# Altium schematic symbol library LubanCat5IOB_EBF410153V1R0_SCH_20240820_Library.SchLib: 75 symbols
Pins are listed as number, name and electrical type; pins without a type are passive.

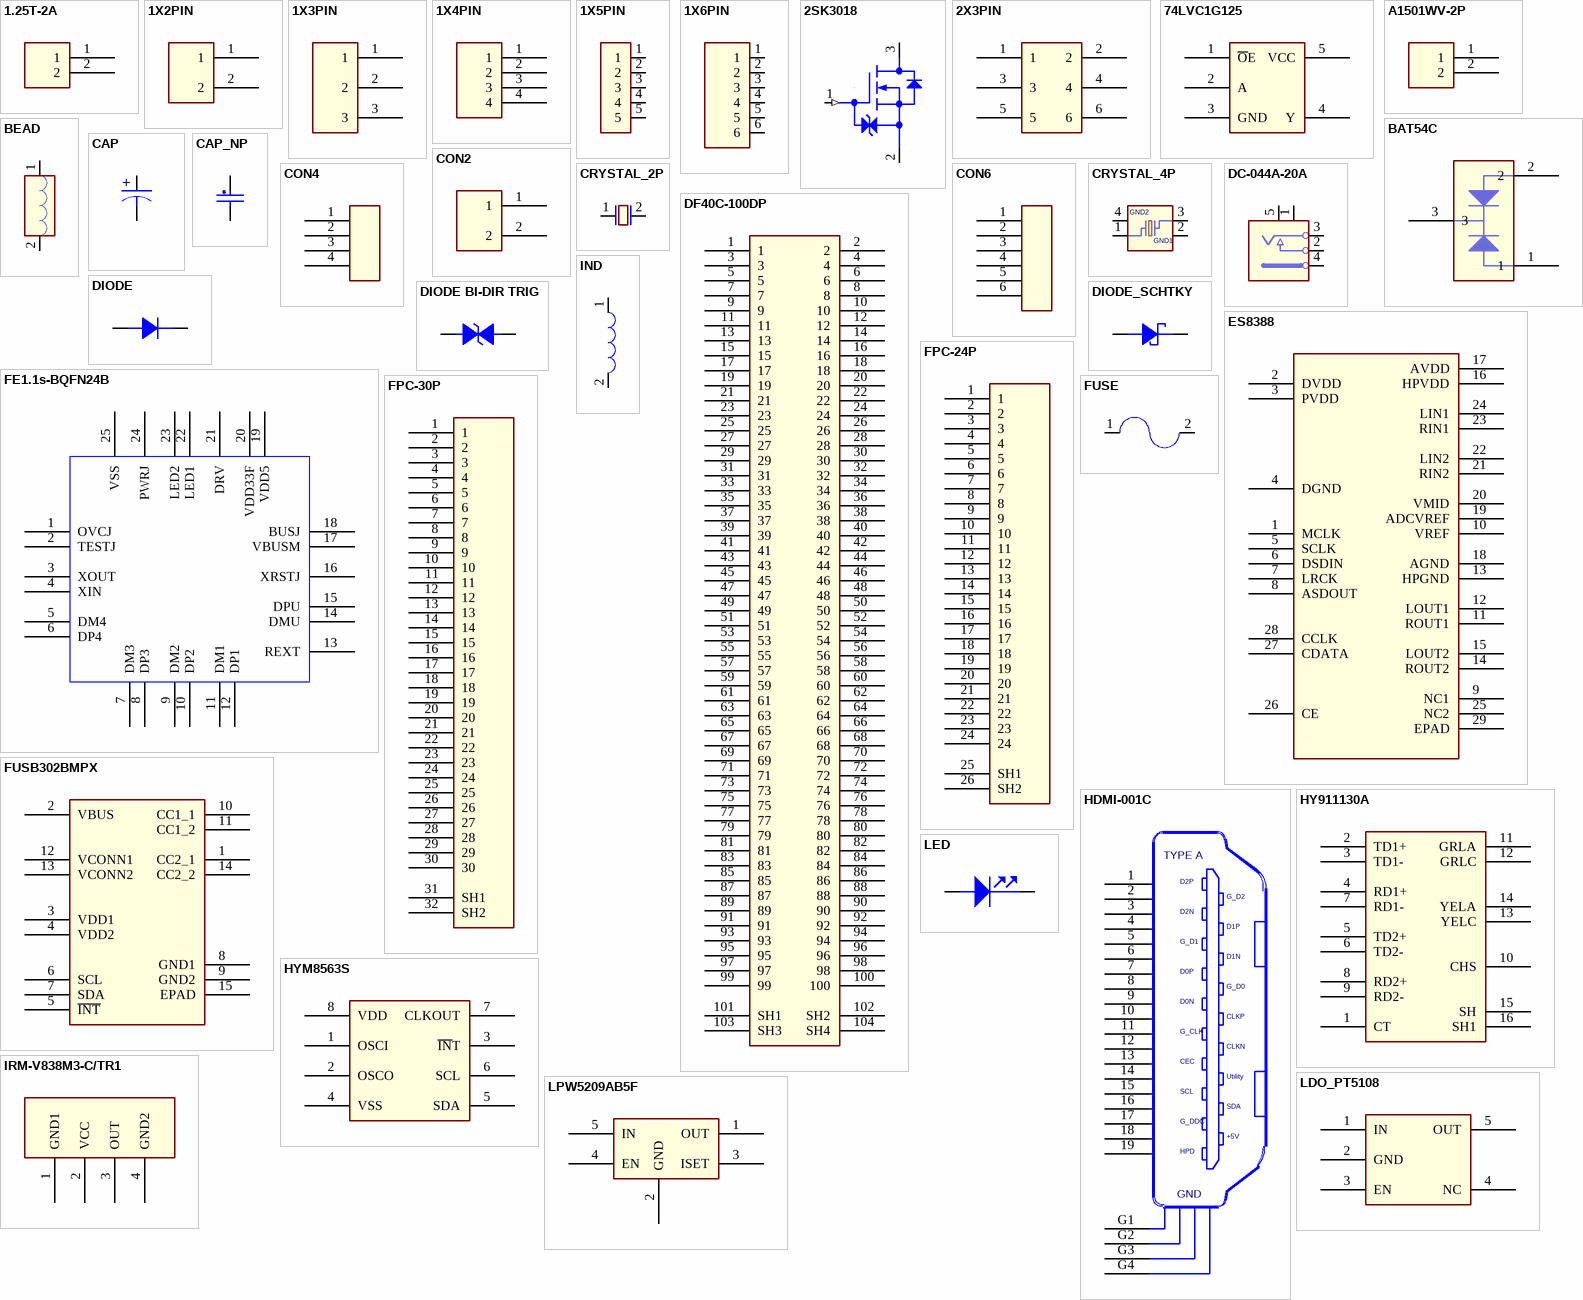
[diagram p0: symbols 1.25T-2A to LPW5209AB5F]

## 1.25T-2A
designator J?
footprint gh1p25_th_2p
pins: 1, 2

## 1X2PIN
designator J?
pins: 1, 2

## 1X3PIN
designator J?
pins: 1, 2, 3

## 1X4PIN
designator J?
pins: 1, 2, 3, 4

## 1X5PIN
designator J?
pins: 1, 2, 3, 4, 5

## 1X6PIN
designator J?
pins: 1, 2, 3, 4, 5, 6

## 2SK3018
designator Q?
CLASS: IC
pins: 1 GATE (in), 2 SOURCE, 3 DRAIN

## 2X3PIN
designator J?
pins: 1, 2, 3, 4, 5, 6

## 74LVC1G125
designator U?
footprint SOT-353
pins: 1 ~{O}E, 2 A, 3 GND, 4 Y, 5 VCC

## A1501WV-2P
designator J?
pins: 1, 2

## BAT54C
designator D?
footprint SOT23
pins: 1, 2, 3

## BEAD
designator L?
CLASS: DISCRETE
pins: 1, 2

## CAP
designator C?
footprint T2012
pins: 1, 2

## CAP_NP
designator C?
CLASS: DISCRETE
pins: 1, 2

## CON2
designator J?
pins: 1, 2

## CON4
designator J?
pins: 1, 2, 3, 4

## CON6
designator J?
pins: 1, 2, 3, 4, 5, 6

## CRYSTAL_2P
designator Y?
footprint 3215
pins: 1, 2

## CRYSTAL_4P
designator Y?
CLASS: IC
pins: 1, 2 GND1 (power), 3, 4 GND2 (power)

## DC-044A-20A
designator J?
footprint dc_in_th_3p_10r1x11r6
pins: 1, 2, 3, 4, 5

## DF40C-100DP
designator J?
pins: 1, 2, 3, 4, 5, 6, 7, 8, 9, 10, 11, 12, 13, 14, 15, 16, 17, 18, 19, 20, 21, 22, 23, 24, 25, 26, 27, 28, 29, 30, 31, 32, 33, 34, 35, 36, 37, 38, 39, 40, 41, 42, 43, 44, 45, 46, 47, 48, 49, 50, 51, 52, 53, 54, 55, 56, 57, 58, 59, 60, 61, 62, 63, 64, 65, 66, 67, 68, 69, 70, 71, 72, 73, 74, 75, 76, 77, 78, 79, 80, 81, 82, 83, 84, 85, 86, 87, 88, 89, 90, 91, 92, 93, 94, 95, 96, 97, 98, 99, 100, 101 SH1, 102 SH2, 103 SH3, 104 SH4

## DIODE
designator D?
pins: 1 K, 2 A

## DIODE BI-DIR TRIG
designator D?
footprint D0603/SMD
pins: 1, 2

## DIODE_SCHTKY
designator D?
CLASS: IC
pins: 1, 2

## ES8388
designator U?
pins: 1 MCLK, 2 DVDD, 3 PVDD, 4 DGND, 5 SCLK, 6 DSDIN, 7 LRCK, 8 ASDOUT, 9 NC1, 10 VREF, 11 ROUT1, 12 LOUT1, 13 HPGND, 14 ROUT2, 15 LOUT2, 16 HPVDD, 17 AVDD, 18 AGND, 19 ADCVREF, 20 VMID, 21 RIN2, 22 LIN2, 23 RIN1, 24 LIN1, 25 NC2, 26 CE, 27 CDATA, 28 CCLK, 29 EPAD

## FE1.1s-BQFN24B
designator U?
pins: 1 OVCJ, 2 TESTJ, 3 XOUT, 4 XIN, 5 DM4, 6 DP4, 7 DM3, 8 DP3, 9 DM2, 10 DP2, 11 DM1, 12 DP1, 13 REXT, 14 DMU, 15 DPU, 16 XRSTJ, 17 VBUSM, 18 BUSJ, 19 VDD5, 20 VDD33F, 21 DRV, 22 LED1, 23 LED2, 24 PWRJ, 25 VSS

## FPC-24P
designator J?
pins: 1, 2, 3, 4, 5, 6, 7, 8, 9, 10, 11, 12, 13, 14, 15, 16, 17, 18, 19, 20, 21, 22, 23, 24, 25 SH1, 26 SH2

## FPC-30P
designator J?
footprint FPC-30P-0P5
pins: 1, 2, 3, 4, 5, 6, 7, 8, 9, 10, 11, 12, 13, 14, 15, 16, 17, 18, 19, 20, 21, 22, 23, 24, 25, 26, 27, 28, 29, 30, 31 SH1, 32 SH2

## FUSB302BMPX
designator U?
pins: 1 CC2_1, 2 VBUS, 3 VDD1, 4 VDD2, 5 ~{INT}, 6 SCL, 7 SDA, 8 GND1, 9 GND2, 10 CC1_1, 11 CC1_2, 12 VCONN1, 13 VCONN2, 14 CC2_2, 15 EPAD

## FUSE
designator F?
pins: 1, 2

## HDMI-001C
designator U?
VPN: 1166-2C105-211; Vendor: Comtek; OriginalSymbolOrigin: (-200,650); CLASS: IO
footprint HDMI-SMD
pins: 1, 2, 3, 4, 5, 6, 7, 8, 9, 10, 11, 12, 13, 14, 15, 16, 17, 18, 19, G1 20, G2 21, G3 22, G4 23

## HY911130A
designator J?
pins: 1 CT, 2 TD1+, 3 TD1-, 4 RD1+, 5 TD2+, 6 TD2-, 7 RD1-, 8 RD2+, 9 RD2-, 10 CHS, 11 GRLA, 12 GRLC, 13 YELC, 14 YELA, 15 SH, 16 SH1

## HYM8563S
designator U?
pins: 1 OSCI, 2 OSCO, 3 ~{IN}T, 4 VSS, 5 SDA, 6 SCL, 7 CLKOUT, 8 VDD

## IND
designator L?
CLASS: DISCRETE
pins: 1, 2

## IRM-V838M3-C/TR1
designator U?
pins: 1 GND1, 2 VCC, 3 OUT, 4 GND2

## LDO_PT5108
designator U?
pins: 1 IN, 2 GND, 3 EN, 4 NC, 5 OUT

## LED
designator LED?
pins: 1 CATHODE, 2 ANODE

## LPW5209AB5F
designator U?
pins: 1 OUT, 2 GND, 3 ISET, 4 EN, 5 IN

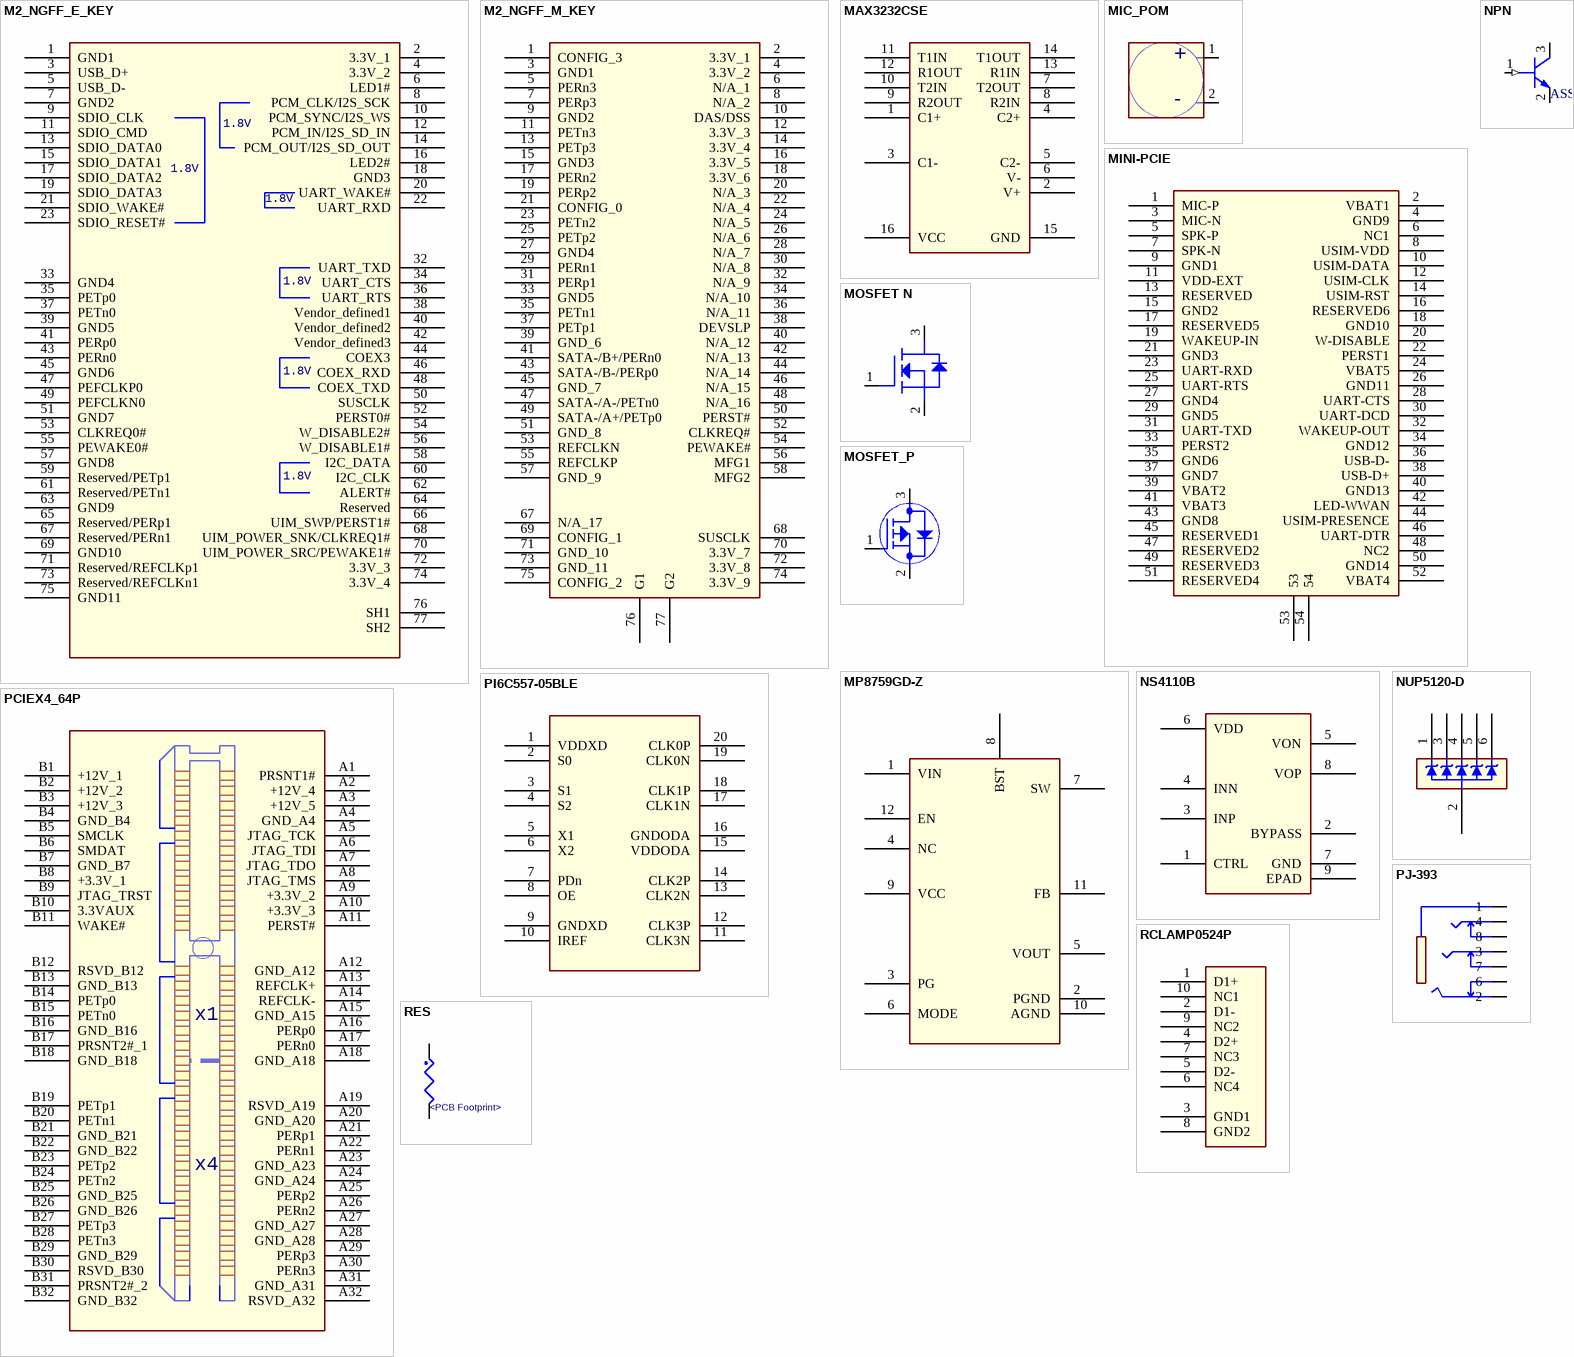
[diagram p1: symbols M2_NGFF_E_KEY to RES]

## M2_NGFF_E_KEY
designator J?
pins: 1 GND1, 2 3.3V_1, 3 USB_D+, 4 3.3V_2, 5 USB_D-, 6 LED1#, 7 GND2, 8 PCM_CLK/I2S_SCK, 9 SDIO_CLK, 10 PCM_SYNC/I2S_WS, 11 SDIO_CMD, 12 PCM_IN/I2S_SD_IN, 13 SDIO_DATA0, 14 PCM_OUT/I2S_SD_OUT, 15 SDIO_DATA1, 16 LED2#, 17 SDIO_DATA2, 18 GND3, 19 SDIO_DATA3, 20 UART_WAKE#, 21 SDIO_WAKE#, 22 UART_RXD, 23 SDIO_RESET#, 32 UART_TXD, 33 GND4, 34 UART_CTS, 35 PETp0, 36 UART_RTS, 37 PETn0, 38 Vendor_defined1, 39 GND5, 40 Vendor_defined2, 41 PERp0, 42 Vendor_defined3, 43 PERn0, 44 COEX3, 45 GND6, 46 COEX_RXD, 47 PEFCLKP0, 48 COEX_TXD, 49 PEFCLKN0, 50 SUSCLK, 51 GND7, 52 PERST0#, 53 CLKREQ0#, 54 W_DISABLE2#, 55 PEWAKE0#, 56 W_DISABLE1#, 57 GND8, 58 I2C_DATA, 59 Reserved/PETp1, 60 I2C_CLK, 61 Reserved/PETn1, 62 ALERT#, 63 GND9, 64 Reserved, 65 Reserved/PERp1, 66 UIM_SWP/PERST1#, 67 Reserved/PERn1, 68 UIM_POWER_SNK/CLKREQ1#, 69 GND10, 70 UIM_POWER_SRC/PEWAKE1#, 71 Reserved/REFCLKp1, 72 3.3V_3, 73 Reserved/REFCLKn1, 74 3.3V_4, 75 GND11, 76 SH1, 77 SH2

## M2_NGFF_M_KEY
designator J?
footprint M2_NGFF_M_KEY
pins: 1 CONFIG_3, 2 3.3V_1, 3 GND1, 4 3.3V_2, 5 PERn3, 6 N/A_1, 7 PERp3, 8 N/A_2, 9 GND2, 10 DAS/DSS, 11 PETn3, 12 3.3V_3, 13 PETp3, 14 3.3V_4, 15 GND3, 16 3.3V_5, 17 PERn2, 18 3.3V_6, 19 PERp2, 20 N/A_3, 21 CONFIG_0, 22 N/A_4, 23 PETn2, 24 N/A_5, 25 PETp2, 26 N/A_6, 27 GND4, 28 N/A_7, 29 PERn1, 30 N/A_8, 31 PERp1, 32 N/A_9, 33 GND5, 34 N/A_10, 35 PETn1, 36 N/A_11, 37 PETp1, 38 DEVSLP, 39 GND_6, 40 N/A_12, 41 SATA-/B+/PERn0, 42 N/A_13, 43 SATA-/B-/PERp0, 44 N/A_14, 45 GND_7, 46 N/A_15, 47 SATA-/A-/PETn0, 48 N/A_16, 49 SATA-/A+/PETp0, 50 PERST#, 51 GND_8, 52 CLKREQ#, 53 REFCLKN, 54 PEWAKE#, 55 REFCLKP, 56 MFG1, 57 GND_9, 58 MFG2, 67 N/A_17, 68 SUSCLK, 69 CONFIG_1, 70 3.3V_7, 71 GND_10, 72 3.3V_8, 73 GND_11, 74 3.3V_9, 75 CONFIG_2, 76 G1, 77 G2

## MAX3232CSE
designator U?
footprint 16
pins: 1 C1+, 2 V+, 3 C1-, 4 C2+, 5 C2-, 6 V-, 7 T2OUT, 8 R2IN, 9 R2OUT, 10 T2IN, 11 T1IN, 12 R1OUT, 13 R1IN, 14 T1OUT, 15 GND (power), 16 VCC (power)

## MIC_POM
designator P?
CLASS: IC
pins: 1 Out, 2 GND

## MINI-PCIE
designator J?
footprint pcie_52p
pins: 1 MIC-P, 2 VBAT1, 3 MIC-N, 4 GND9, 5 SPK-P, 6 NC1, 7 SPK-N, 8 USIM-VDD, 9 GND1, 10 USIM-DATA, 11 VDD-EXT, 12 USIM-CLK, 13 RESERVED, 14 USIM-RST, 15 GND2, 16 RESERVED6, 17 RESERVED5, 18 GND10, 19 WAKEUP-IN, 20 W-DISABLE, 21 GND3, 22 PERST1, 23 UART-RXD, 24 VBAT5, 25 UART-RTS, 26 GND11, 27 GND4, 28 UART-CTS, 29 GND5, 30 UART-DCD, 31 UART-TXD, 32 WAKEUP-OUT, 33 PERST2, 34 GND12, 35 GND6, 36 USB-D-, 37 GND7, 38 USB-D+, 39 VBAT2, 40 GND13, 41 VBAT3, 42 LED-WWAN, 43 GND8, 44 USIM-PRESENCE, 45 RESERVED1, 46 UART-DTR, 47 RESERVED2, 48 NC2, 49 RESERVED3, 50 GND14, 51 RESERVED4, 52 VBAT4, 53, 54

## MOSFET N
designator Q?
footprint SOT23
pins: 1 GATE, 2 SOURCE, 3 DRAIN

## MOSFET_P
designator Q?
CLASS: IC
pins: 1 GATE, 2 SOURCE, 3 DRAIN

## MP8759GD-Z
designator U?
pins: 1 VIN, 2 PGND, 3 PG, 4 NC, 5 VOUT, 6 MODE, 7 SW, 8 BST, 9 VCC, 10 AGND, 11 FB, 12 EN

## NPN
designator Q?
CLASS: IC
pins: 1 BASE (in), 2 EMITTER, 3 COLLECTOR

## NS4110B
designator U?
pins: 1 CTRL, 2 BYPASS, 3 INP, 4 INN, 5 VON, 6 VDD, 7 GND, 8 VOP, 9 EPAD

## NUP5120-D
designator U?
pins: 1, 2, 3, 4, 5, 6

## PCIEX4_64P
designator J?
pins: A1 PRSNT1#, A2 +12V_4, A3 +12V_5, A4 GND_A4, A5 JTAG_TCK, A6 JTAG_TDI, A7 JTAG_TDO, A8 JTAG_TMS, A9 +3.3V_2, A10 +3.3V_3, A11 PERST#, A12 GND_A12, A13 REFCLK+, A14 REFCLK-, A15 GND_A15, A16 PERp0, A17 PERn0, A18 GND_A18, A19 RSVD_A19, A20 GND_A20, A21 PERp1, A22 PERn1, A23 GND_A23, A24 GND_A24, A25 PERp2, A26 PERn2, A27 GND_A27, A28 GND_A28, A29 PERp3, A30 PERn3, A31 GND_A31, A32 RSVD_A32, B1 +12V_1, B2 +12V_2, B3 +12V_3, B4 GND_B4, B5 SMCLK, B6 SMDAT, B7 GND_B7, B8 +3.3V_1, B9 JTAG_TRST, B10 3.3VAUX, B11 WAKE#, B12 RSVD_B12, B13 GND_B13, B14 PETp0, B15 PETn0, B16 GND_B16, B17 PRSNT2#_1, B18 GND_B18, B19 PETp1, B20 PETn1, B21 GND_B21, B22 GND_B22, B23 PETp2, B24 PETn2, B25 GND_B25, B26 GND_B26, B27 PETp3, B28 PETn3, B29 GND_B29, B30 RSVD_B30, B31 PRSNT2#_2, B32 GND_B32

## PI6C557-05BLE
designator U?
footprint TSSOP20
pins: 1 VDDXD, 2 S0, 3 S1, 4 S2, 5 X1, 6 X2, 7 PDn, 8 OE, 9 GNDXD, 10 IREF, 11 CLK3N, 12 CLK3P, 13 CLK2N, 14 CLK2P, 15 VDDODA, 16 GNDODA, 17 CLK1N, 18 CLK1P, 19 CLK0N, 20 CLK0P

## PJ-393
designator J?
footprint audio_smd_7p_6r0x8r8
pins: 1, 2, 3, 4, 6, 7, 8

## RCLAMP0524P
designator U?
pins: 1 D1+, 2 D1-, 3 GND1, 4 D2+, 5 D2-, 6 NC4, 7 NC3, 8 GND2, 9 NC2, 10 NC1

## RES
designator R?  PCB Footprint: <PCB Footprint>
CLASS: DISCRETE
pins: 1, 2

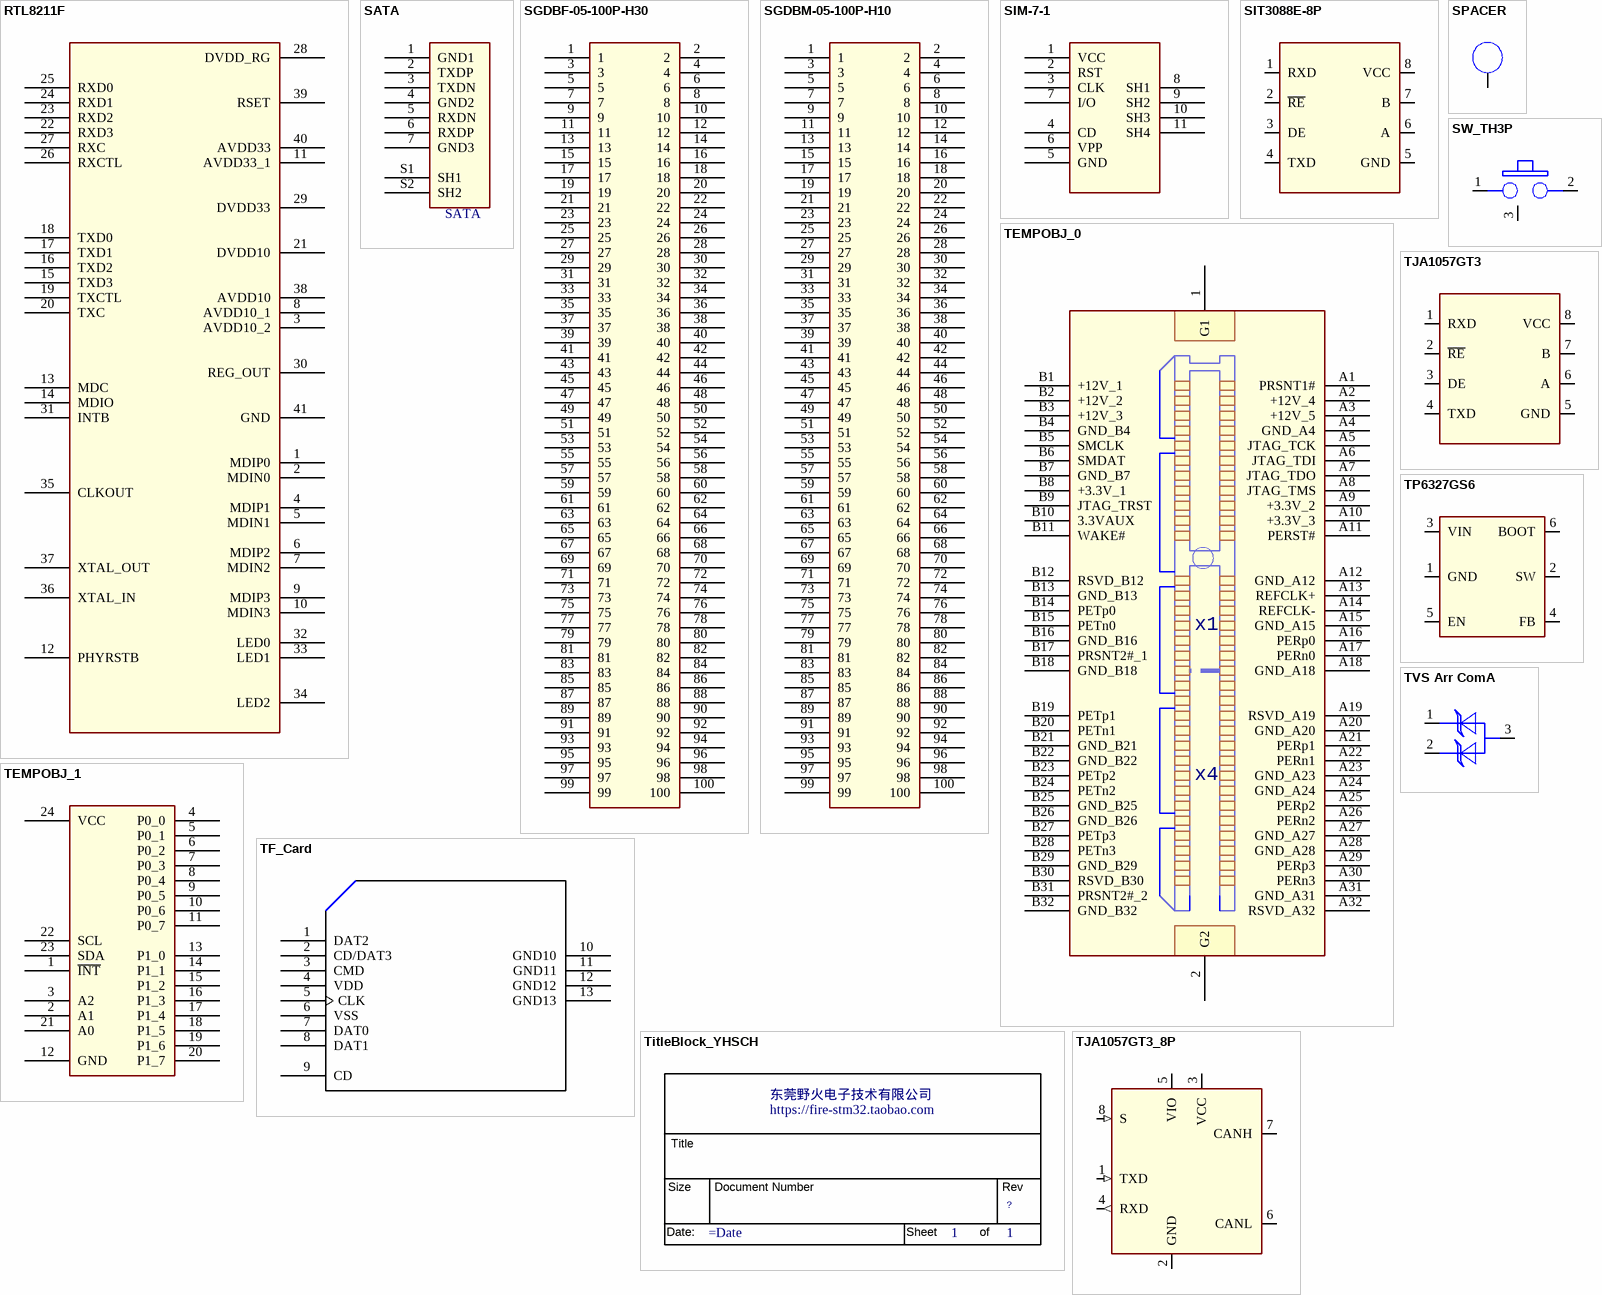
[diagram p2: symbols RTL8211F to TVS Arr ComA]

## RTL8211F
designator U?
pins: 1 MDIP0, 2 MDIN0, 3 AVDD10_2, 4 MDIP1, 5 MDIN1, 6 MDIP2, 7 MDIN2, 8 AVDD10_1, 9 MDIP3, 10 MDIN3, 11 AVDD33_1, 12 PHYRSTB, 13 MDC, 14 MDIO, 15 TXD3, 16 TXD2, 17 TXD1, 18 TXD0, 19 TXCTL, 20 TXC, 21 DVDD10, 22 RXD3, 23 RXD2, 24 RXD1, 25 RXD0, 26 RXCTL, 27 RXC, 28 DVDD_RG, 29 DVDD33, 30 REG_OUT, 31 INTB, 32 LED0, 33 LED1, 34 LED2, 35 CLKOUT, 36 XTAL_IN, 37 XTAL_OUT, 38 AVDD10, 39 RSET, 40 AVDD33, 41 GND

## SATA
designator J?
footprint ssata_v
pins: 1 GND1, 2 TXDP, 3 TXDN, 4 GND2, 5 RXDN, 6 RXDP, 7 GND3, S1 SH1 (power), S2 SH2 (power)

## SGDBF-05-100P-H30
designator J?
pins: 1, 2, 3, 4, 5, 6, 7, 8, 9, 10, 11, 12, 13, 14, 15, 16, 17, 18, 19, 20, 21, 22, 23, 24, 25, 26, 27, 28, 29, 30, 31, 32, 33, 34, 35, 36, 37, 38, 39, 40, 41, 42, 43, 44, 45, 46, 47, 48, 49, 50, 51, 52, 53, 54, 55, 56, 57, 58, 59, 60, 61, 62, 63, 64, 65, 66, 67, 68, 69, 70, 71, 72, 73, 74, 75, 76, 77, 78, 79, 80, 81, 82, 83, 84, 85, 86, 87, 88, 89, 90, 91, 92, 93, 94, 95, 96, 97, 98, 99, 100

## SGDBM-05-100P-H10
designator J?
pins: 1, 2, 3, 4, 5, 6, 7, 8, 9, 10, 11, 12, 13, 14, 15, 16, 17, 18, 19, 20, 21, 22, 23, 24, 25, 26, 27, 28, 29, 30, 31, 32, 33, 34, 35, 36, 37, 38, 39, 40, 41, 42, 43, 44, 45, 46, 47, 48, 49, 50, 51, 52, 53, 54, 55, 56, 57, 58, 59, 60, 61, 62, 63, 64, 65, 66, 67, 68, 69, 70, 71, 72, 73, 74, 75, 76, 77, 78, 79, 80, 81, 82, 83, 84, 85, 86, 87, 88, 89, 90, 91, 92, 93, 94, 95, 96, 97, 98, 99, 100

## SIM-7-1
designator U?
pins: 1 VCC, 2 RST, 3 CLK, 4 CD, 5 GND, 6 VPP, 7 I/O, 8 SH1, 9 SH2, 10 SH3, 11 SH4

## SIT3088E-8P
designator U?
CLASS: IC
pins: 1 RXD, 2 ~{RE}, 3 DE, 4 TXD, 5 GND, 6 A, 7 B, 8 VCC

## SPACER
designator SS?
CLASS: IC
pins: 1 NC_1

## SW_TH3P
designator SW?  (value not drawn)
CLASS: IC
pins: 1 A1, 2 B1, 3 GND1

## TEMPOBJ_0
designator J?
pins: 1 G1, 2 G2, A1 PRSNT1#, A2 +12V_4, A3 +12V_5, A4 GND_A4, A5 JTAG_TCK, A6 JTAG_TDI, A7 JTAG_TDO, A8 JTAG_TMS, A9 +3.3V_2, A10 +3.3V_3, A11 PERST#, A12 GND_A12, A13 REFCLK+, A14 REFCLK-, A15 GND_A15, A16 PERp0, A17 PERn0, A18 GND_A18, A19 RSVD_A19, A20 GND_A20, A21 PERp1, A22 PERn1, A23 GND_A23, A24 GND_A24, A25 PERp2, A26 PERn2, A27 GND_A27, A28 GND_A28, A29 PERp3, A30 PERn3, A31 GND_A31, A32 RSVD_A32, B1 +12V_1, B2 +12V_2, B3 +12V_3, B4 GND_B4, B5 SMCLK, B6 SMDAT, B7 GND_B7, B8 +3.3V_1, B9 JTAG_TRST, B10 3.3VAUX, B11 WAKE#, B12 RSVD_B12, B13 GND_B13, B14 PETp0, B15 PETn0, B16 GND_B16, B17 PRSNT2#_1, B18 GND_B18, B19 PETp1, B20 PETn1, B21 GND_B21, B22 GND_B22, B23 PETp2, B24 PETn2, B25 GND_B25, B26 GND_B26, B27 PETp3, B28 PETn3, B29 GND_B29, B30 RSVD_B30, B31 PRSNT2#_2, B32 GND_B32

## TEMPOBJ_1
designator U?
pins: 1 ~{INT}, 2 A1, 3 A2, 4 P0_0, 5 P0_1, 6 P0_2, 7 P0_3, 8 P0_4, 9 P0_5, 10 P0_6, 11 P0_7, 12 GND, 13 P1_0, 14 P1_1, 15 P1_2, 16 P1_3, 17 P1_4, 18 P1_5, 19 P1_6, 20 P1_7, 21 A0, 22 SCL, 23 SDA, 24 VCC

## TF_Card
designator J?
CLASS: IO
pins: 1 DAT2, 2 CD/DAT3, 3 CMD, 4 VDD (power), 5 CLK, 6 VSS (power), 7 DAT0, 8 DAT1, 9 CD, 10 GND10, 11 GND11, 12 GND12, 13 GND13

## TitleBlock_YHSCH
designator *  OrgName: 东莞野火电子技术有限公司  Page Number: 1  (hidden comment: *)  (graphical)

## TJA1057GT3
designator U?
CLASS: IC
pins: 1 RXD, 2 ~{RE}, 3 DE, 4 TXD, 5 GND, 6 A, 7 B, 8 VCC

## TJA1057GT3_8P
designator U?
CLASS: IC
pins: 1 TXD (in), 2 GND (power), 3 VCC (power), 4 RXD (out), 5 VIO (power), 6 CANL (io), 7 CANH (io), 8 S (in)

## TP6327GS6
designator U?
pins: 1 GND, 2 SW, 3 VIN, 4 FB, 5 EN, 6 BOOT

## TVS Arr ComA
designator DN?
pins: 1 C1, 2 C2, 3 A

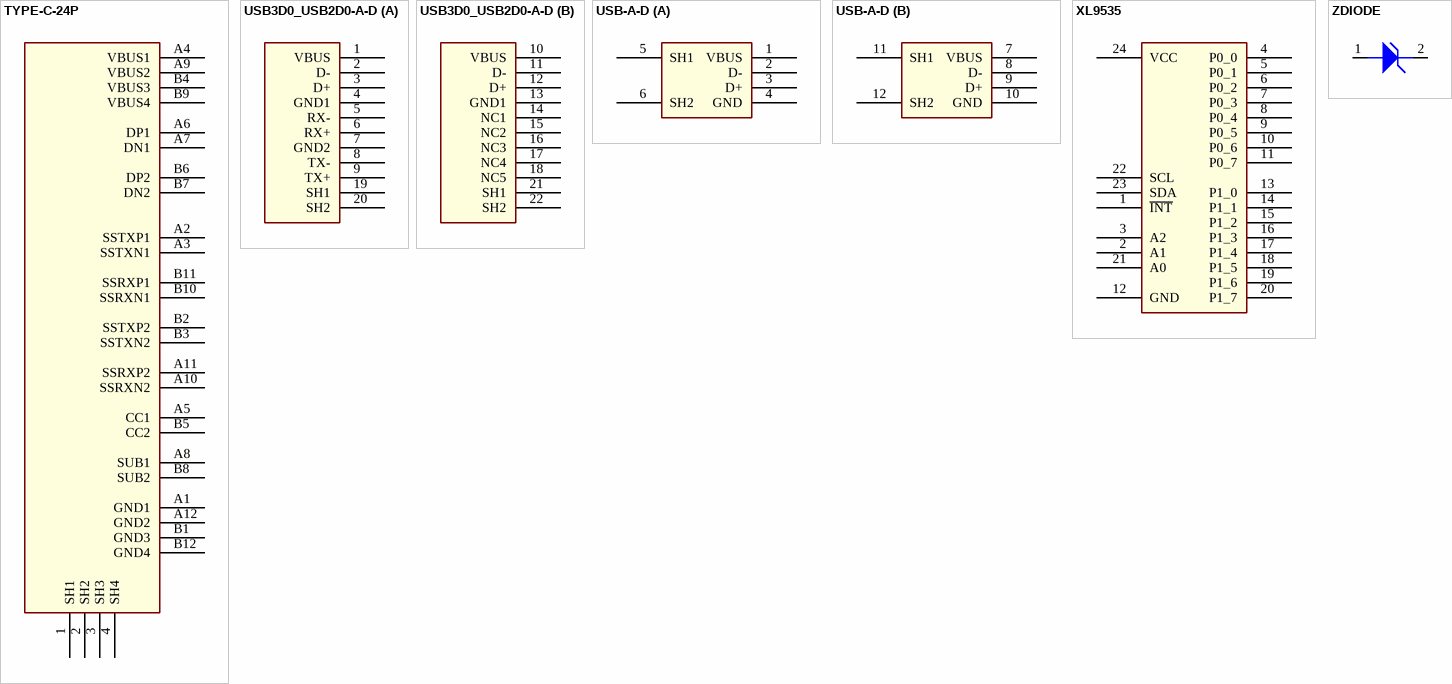
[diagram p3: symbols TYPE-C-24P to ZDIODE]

## TYPE-C-24P
designator J?
pins: 1 SH1, 2 SH2, 3 SH3, 4 SH4, A1 GND1, A2 SSTXP1, A3 SSTXN1, A4 VBUS1, A5 CC1, A6 DP1, A7 DN1, A8 SUB1, A9 VBUS2, A10 SSRXN2, A11 SSRXP2, A12 GND2, B1 GND3, B2 SSTXP2, B3 SSTXN2, B4 VBUS3, B5 CC2, B6 DP2, B7 DN2, B8 SUB2, B9 VBUS4, B10 SSRXN1, B11 SSRXP1, B12 GND4

## USB3D0_USB2D0-A-D
designator J?
footprint USB3D0-AF-18P
part A pins: 1 VBUS, 2 D-, 3 D+, 4 GND1, 5 RX-, 6 RX+, 7 GND2, 8 TX-, 9 TX+, 19 SH1, 20 SH2
part B pins: 10 VBUS, 11 D-, 12 D+, 13 GND1, 14 NC1, 15 NC2, 16 NC3, 17 NC4, 18 NC5, 21 SH1, 22 SH2

## USB-A-D
designator J?
footprint USB-A-D
part A pins: 1 VBUS, 2 D-, 3 D+, 4 GND, 5 SH1, 6 SH2
part B pins: 7 VBUS, 8 D-, 9 D+, 10 GND, 11 SH1, 12 SH2

## XL9535
designator U?
pins: 1 ~{INT}, 2 A1, 3 A2, 4 P0_0, 5 P0_1, 6 P0_2, 7 P0_3, 8 P0_4, 9 P0_5, 10 P0_6, 11 P0_7, 12 GND, 13 P1_0, 14 P1_1, 15 P1_2, 16 P1_3, 17 P1_4, 18 P1_5, 19 P1_6, 20 P1_7, 21 A0, 22 SCL, 23 SDA, 24 VCC

## ZDIODE
designator D?
CLASS: IC
pins: 1 ANODE, 2 CATHODE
